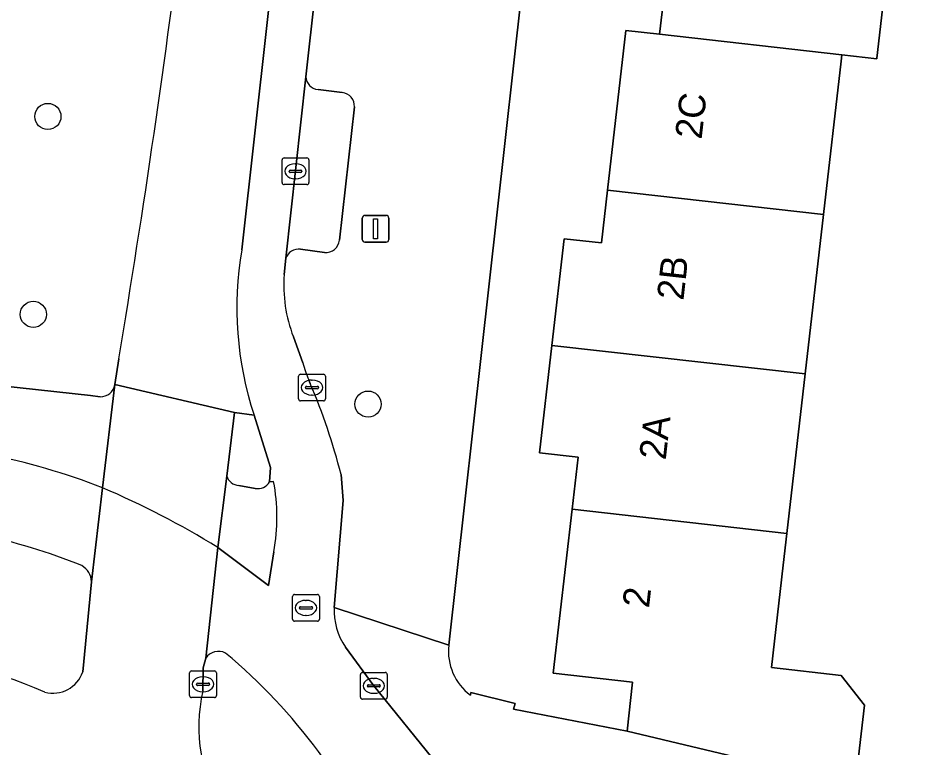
# Model space of a CAD drawing. Extents: x 162026 to 163502, y 387295 to 388169.
# Drawn here: x 162355.04 to 162389.15, y 387412.57 to 387439.84 of the extents above; entities that cross this region are included whole.
import ezdxf

# ---------------------------------------------------------------- set-up
doc = ezdxf.new("R2010")
doc.units = 0
for name, color, linetype in [('IMGEO_Berm_groen', 7, 'Continuous'), ('IMGEO_Boom', 7, 'Continuous'), ('IMGEO_Erf', 7, 'Continuous'), ('IMGEO_Fietspad_gesloten', 7, 'Continuous'), ('IMGEO_Fietspad_open', 7, 'Continuous'), ('IMGEO_Kolk', 7, 'Continuous'), ('IMGEO_Lichtmast', 7, 'Continuous'), ('IMGEO_Pand', 7, 'Continuous'), ('IMGEO_Pand_nummerreeks', 7, 'Continuous'), ('IMGEO_Parkeervlak_open', 7, 'Continuous'), ('IMGEO_Rijbaan_lokaal_gesloten', 7, 'Continuous'), ('IMGEO_Rioolput', 7, 'Continuous'), ('IMGEO_Verkeerseiland_gesloten', 7, 'Continuous'), ('IMGEO_Verkeerseiland_groen', 7, 'Continuous'), ('IMGEO_Voetpad_open', 7, 'Continuous')]:
    doc.layers.add(name, color=color, linetype=linetype)

msp = doc.modelspace()

# ---------------------------------------------------------------- linework, layer by layer
at = {"layer": 'IMGEO_Berm_groen'}
for points in [[(162358.65, 387426.145), (162358.797, 387427.106)], [(162350.307, 387426.551), (162357.748, 387425.733), (162358.101, 387425.69)]]:
    msp.add_lwpolyline(points, dxfattribs=at)
for centre, radius, start, end in [((161972.176, 387492.017), 392.032, 350.46924, 352.96278), ((162358.124, 387426.221), 0.531, 267.5182, 351.7843)]:
    msp.add_arc(centre, radius, start, end, dxfattribs=at)
at = {"layer": 'IMGEO_Boom'}
for centre in [(162356.148, 387436.17), (162355.605, 387428.77), (162368.117, 387425.414)]:
    msp.add_circle(centre, 0.489, dxfattribs=at)
at = {"layer": 'IMGEO_Erf'}
for points in [[(162377.752, 387439.384), (162379.017, 387439.241), (162379.247, 387441.236), (162378.017, 387441.378), (162378.471, 387445.326), (162378.919, 387449.221), (162380.223, 387449.071), (162380.463, 387451.159), (162381.147, 387457.113), (162383.889, 387456.798), (162384.164, 387459.183), (162377.94, 387459.884), (162376.15, 387460.086), (162376.131, 387460.234), (162376.03, 387460.239), (162375.655, 387456.942), (162371.134, 387416.396)], [(162391.38, 387449.925), (162388.505, 387450.25), (162387.82, 387444.289), (162387.137, 387438.348), (162387.134, 387438.321), (162385.833, 387438.468), (162385.806, 387438.236), (162385.147, 387432.501), (162384.462, 387426.543), (162383.777, 387420.583), (162383.641, 387419.398), (162383.201, 387415.569), (162385.799, 387415.271), (162386.677, 387414.163), (162386.331, 387411.152), (162391.662, 387409.78)], [(162371.947, 387414.533), (162371.957, 387414.634), (162373.616, 387414.217), (162373.56, 387414.003), (162377.809, 387413.191), (162377.999, 387415.013), (162375.039, 387415.353), (162375.743, 387421.481), (162375.967, 387423.431), (162374.533, 387423.596), (162374.994, 387427.606), (162375.453, 387431.599), (162376.839, 387431.44), (162377.066, 387433.415), (162377.752, 387439.384)]]:
    msp.add_lwpolyline(points, dxfattribs=at)
msp.add_arc((162373.162, 387416.172), 2.04, 173.6926, 233.4596, dxfattribs=at)
at = {"layer": 'IMGEO_Fietspad_gesloten'}
for points in [[(162367.941, 387456.884), (162367.962, 387457.104), (162368.361, 387460.854), (162368.714, 387463.921), (162373.113, 387503.254), (162371.444, 387503.441), (162363.403, 387431.184)], [(162364.983, 387430.263), (162365.039, 387430.868), (162365.797, 387437.657), (162367.941, 387456.884)], [(162365.683, 387426.954), (162365.325, 387427.933)], [(162365.958, 387426.183), (162365.928, 387426.252), (162365.9, 387426.321)], [(162363.857, 387425.002), (162364.477, 387423.042), (162364.435, 387422.512), (162364.585, 387422.527)], [(162366.853, 387417.815), (162367.19, 387421.816), (162367.108, 387422.786)], [(162364.59, 387419.896), (162364.392, 387418.637), (162362.502, 387420.059), (162362.048, 387415.912)], [(162370.708, 387411.942), (162368.334, 387414.881), (162367.279, 387416.327)]]:
    msp.add_lwpolyline(points, dxfattribs=at)
for centre, radius, start, end in [((162375.99, 387429.001), 12.775, 170.1593, 198.2411), ((162370.276, 387429.85), 5.309, 175.5359, 201.1647), ((162371.018, 387428.429), 5.535, 195.4568, 202.3879), ((162344.425, 387417), 23.409, 14.3094, 23.096), ((162357.756, 387421.199), 6.957, 349.2097, 11.0081), ((162369.256, 387417.698), 2.406, 177.2096, 214.7422), ((162362.526, 387415.6), 0.571, 62.3062, 146.8162), ((162349.148, 387399.739), 21.306, 22.8824, 50.1851)]:
    msp.add_arc(centre, radius, start, end, dxfattribs=at)
at = {"layer": 'IMGEO_Fietspad_open'}
msp.add_lwpolyline([(162357.784, 387418.776), (162358.194, 387422.286)], dxfattribs=at)
for centre, radius, start, end in [((162349.072, 387398.916), 25.087, 68.6787, 89.1056), ((162349.094, 387398.822), 22.176, 67.942, 88.6487), ((162357.023, 387418.725), 0.763, 3.8485, 58.444)]:
    msp.add_arc(centre, radius, start, end, dxfattribs=at)
at = {"layer": 'IMGEO_Kolk'}
for p, q in [((162364.905, 387433.695), (162364.905, 387434.547)), ((162364.98, 387434.621), (162365.832, 387434.621)), ((162365.906, 387434.547), (162365.906, 387433.695)), ((162365.164, 387434.115), (162365.164, 387434.127)), ((162365.207, 387434.164), (162365.605, 387434.164)), ((162365.393, 387434.401), (162365.418, 387434.401)), ((162365.648, 387434.127), (162365.648, 387434.115)), ((162365.602, 387434.078), (162365.204, 387434.078)), ((162365.416, 387433.841), (162365.391, 387433.841)), ((162365.832, 387433.621), (162364.98, 387433.621)), ((162365.521, 387425.608), (162365.521, 387426.46)), ((162365.596, 387426.534), (162366.448, 387426.534)), ((162366.009, 387426.314), (162366.034, 387426.314)), ((162366.522, 387426.46), (162366.522, 387425.608)), ((162365.78, 387426.028), (162365.78, 387426.04)), ((162366.218, 387425.991), (162365.82, 387425.991)), ((162365.823, 387426.077), (162366.221, 387426.077)), ((162366.264, 387426.04), (162366.264, 387426.028)), ((162366.032, 387425.754), (162366.007, 387425.754)), ((162366.448, 387425.534), (162365.596, 387425.534)), ((162361.447, 387414.515), (162361.447, 387415.367)), ((162361.522, 387415.441), (162362.374, 387415.441)), ((162362.448, 387415.367), (162362.448, 387414.515)), ((162367.908, 387415.381), (162368.76, 387415.381)), ((162361.935, 387415.221), (162361.96, 387415.221)), ((162367.833, 387414.455), (162367.833, 387415.307)), ((162368.321, 387415.161), (162368.346, 387415.161)), ((162368.834, 387415.307), (162368.834, 387414.455)), ((162361.706, 387414.935), (162361.706, 387414.947)), ((162362.144, 387414.898), (162361.746, 387414.898)), ((162361.749, 387414.984), (162362.147, 387414.984)), ((162361.958, 387414.661), (162361.933, 387414.661)), ((162362.19, 387414.947), (162362.19, 387414.935)), ((162368.092, 387414.875), (162368.092, 387414.887)), ((162368.53, 387414.838), (162368.132, 387414.838)), ((162368.135, 387414.924), (162368.533, 387414.924)), ((162368.576, 387414.887), (162368.576, 387414.875)), ((162362.374, 387414.441), (162361.522, 387414.441)), ((162368.76, 387414.381), (162367.908, 387414.381)), ((162368.344, 387414.601), (162368.319, 387414.601))]:
    msp.add_line(p, q, dxfattribs=at)
for points in [[(162364.905, 387433.695), (162364.905, 387434.547)], [(162364.98, 387434.621), (162365.832, 387434.621)], [(162365.906, 387434.547), (162365.906, 387433.695)], [(162365.832, 387433.621), (162364.98, 387433.621)], [(162365.521, 387425.608), (162365.521, 387426.46)], [(162365.596, 387426.534), (162366.448, 387426.534)], [(162366.522, 387426.46), (162366.522, 387425.608)], [(162366.448, 387425.534), (162365.596, 387425.534)], [(162361.447, 387414.515), (162361.447, 387415.367)], [(162361.522, 387415.441), (162362.374, 387415.441)], [(162362.448, 387415.367), (162362.448, 387414.515)], [(162367.908, 387415.381), (162368.76, 387415.381)], [(162367.833, 387414.455), (162367.833, 387415.307)], [(162368.834, 387415.307), (162368.834, 387414.455)], [(162362.374, 387414.441), (162361.522, 387414.441)], [(162368.76, 387414.381), (162367.908, 387414.381)]]:
    msp.add_lwpolyline(points, dxfattribs=at)
for centre, radius, start, end in [((162364.982, 387434.545), 0.0765, 91.552, 178.448), ((162364.982, 387434.545), 0.0765, 91.552, 178.448), ((162365.83, 387434.545), 0.0765, 1.552, 88.448), ((162365.83, 387434.545), 0.0765, 1.552, 88.448), ((162365.204, 387434.124), 0.0403, 85.8775, 175.7526), ((162365.201, 387434.114), 0.0366, 178.938, 274.7102), ((162365.605, 387434.121), 0.043, 264.8664, 352.4533), ((162365.609, 387434.126), 0.0386, 1.7309, 96.639), ((162364.982, 387433.697), 0.0765, 181.552, 268.448), ((162364.982, 387433.697), 0.0765, 181.552, 268.448), ((162365.83, 387433.697), 0.0765, 271.552, 358.448), ((162365.83, 387433.697), 0.0765, 271.552, 358.448), ((162365.598, 387426.458), 0.0765, 91.552, 178.448), ((162365.598, 387426.458), 0.0765, 91.552, 178.448), ((162366.446, 387426.458), 0.0765, 1.552, 88.448), ((162366.446, 387426.458), 0.0765, 1.552, 88.448), ((162365.82, 387426.037), 0.0403, 85.8775, 175.7526), ((162365.817, 387426.027), 0.0366, 178.938, 274.7102), ((162366.221, 387426.034), 0.043, 264.8664, 352.4533), ((162366.225, 387426.039), 0.0386, 1.7309, 96.639), ((162365.598, 387425.61), 0.0765, 181.552, 268.448), ((162365.598, 387425.61), 0.0765, 181.552, 268.448), ((162366.446, 387425.61), 0.0765, 271.552, 358.448), ((162366.446, 387425.61), 0.0765, 271.552, 358.448), ((162361.524, 387415.365), 0.0765, 91.552, 178.448), ((162361.524, 387415.365), 0.0765, 91.552, 178.448), ((162362.372, 387415.365), 0.0765, 1.552, 88.448), ((162362.372, 387415.365), 0.0765, 1.552, 88.448), ((162367.91, 387415.305), 0.0765, 91.552, 178.448), ((162367.91, 387415.305), 0.0765, 91.552, 178.448), ((162368.758, 387415.305), 0.0765, 1.552, 88.448), ((162368.758, 387415.305), 0.0765, 1.552, 88.448), ((162361.746, 387414.944), 0.0403, 85.8775, 175.7526), ((162361.743, 387414.934), 0.0366, 178.938, 274.7102), ((162362.147, 387414.941), 0.043, 264.8664, 352.4533), ((162362.151, 387414.946), 0.0386, 1.7309, 96.639), ((162368.132, 387414.884), 0.0403, 85.8775, 175.7526), ((162368.129, 387414.874), 0.0366, 178.938, 274.7102), ((162368.533, 387414.881), 0.043, 264.8664, 352.4533), ((162368.537, 387414.886), 0.0386, 1.7309, 96.639), ((162361.524, 387414.517), 0.0765, 181.552, 268.448), ((162361.524, 387414.517), 0.0765, 181.552, 268.448), ((162362.372, 387414.517), 0.0765, 271.552, 358.448), ((162362.372, 387414.517), 0.0765, 271.552, 358.448), ((162367.91, 387414.457), 0.0765, 181.552, 268.448), ((162367.91, 387414.457), 0.0765, 181.552, 268.448), ((162368.758, 387414.457), 0.0765, 271.552, 358.448), ((162368.758, 387414.457), 0.0765, 271.552, 358.448)]:
    msp.add_arc(centre, radius, start, end, dxfattribs=at)
for centre, major_axis, ratio, start_param, end_param in [((162365.392, 387434.121), (-0.387, 0.002), 0.722429, 4.712389, 7.853982), ((162365.417, 387434.121), (-0.39, 0.002), 0.717154, 1.570796, 4.712389), ((162366.008, 387426.034), (-0.387, 0.002), 0.722429, 4.712389, 7.853982), ((162366.033, 387426.034), (-0.39, 0.002), 0.717154, 1.570796, 4.712389), ((162361.934, 387414.941), (-0.387, 0.002), 0.722429, 4.712389, 7.853982), ((162361.959, 387414.941), (-0.39, 0.002), 0.717154, 1.570796, 4.712389), ((162368.32, 387414.881), (-0.387, 0.002), 0.722429, 4.712389, 7.853982), ((162368.345, 387414.881), (-0.39, 0.002), 0.717154, 1.570796, 4.712389)]:
    msp.add_ellipse(centre, major_axis=major_axis, ratio=ratio, start_param=start_param, end_param=end_param, dxfattribs=at)
at = {"layer": 'IMGEO_Lichtmast'}
for p, q in [((162368.003, 387432.469), (162368.793, 387432.469)), ((162368.793, 387432.469), (162368.003, 387432.469)), ((162367.903, 387431.569), (162367.903, 387432.369)), ((162367.903, 387432.369), (162367.903, 387431.569)), ((162368.893, 387432.369), (162368.893, 387431.569)), ((162368.893, 387431.569), (162368.893, 387432.369)), ((162368.793, 387431.469), (162368.003, 387431.469)), ((162368.003, 387431.469), (162368.793, 387431.469))]:
    msp.add_line(p, q, dxfattribs=at)
msp.add_lwpolyline([(162368.323, 387432.344), (162368.473, 387432.344), (162368.473, 387431.594), (162368.323, 387431.594), (162368.323, 387432.344)], dxfattribs=at)
for centre, start, end in [((162368.003, 387432.369), 90, 180), ((162368.003, 387432.369), 90, 180), ((162368.793, 387432.369), 0, 90), ((162368.793, 387432.369), 360, 90), ((162368.003, 387431.569), 180, 270), ((162368.003, 387431.569), 180, 270), ((162368.793, 387431.569), 270, 0), ((162368.793, 387431.569), 270, 0)]:
    msp.add_arc(centre, 0.1, start, end, dxfattribs=at)
at = {"layer": 'IMGEO_Pand'}
for points in [[(162387.82, 387444.289), (162378.471, 387445.326), (162378.017, 387441.378), (162379.247, 387441.236), (162379.017, 387439.241), (162385.833, 387438.468), (162387.134, 387438.321), (162387.137, 387438.348)], [(162385.806, 387438.236), (162385.833, 387438.468), (162379.017, 387439.241), (162377.752, 387439.384), (162377.066, 387433.415), (162385.147, 387432.501)], [(162384.462, 387426.543), (162385.147, 387432.501), (162377.066, 387433.415), (162376.839, 387431.44), (162375.453, 387431.599), (162374.994, 387427.606)], [(162374.994, 387427.606), (162374.533, 387423.596), (162375.967, 387423.431), (162375.743, 387421.481), (162383.777, 387420.583), (162384.462, 387426.543)], [(162386.331, 387411.152), (162386.677, 387414.163), (162385.799, 387415.271), (162383.201, 387415.569), (162383.641, 387419.398), (162383.777, 387420.583), (162375.743, 387421.481), (162375.039, 387415.353), (162377.999, 387415.013), (162377.809, 387413.191)]]:
    msp.add_lwpolyline(points, close=True, dxfattribs=at)
at = {"layer": 'IMGEO_Parkeervlak_open'}
for points in [[(162365.797, 387437.657), (162365.039, 387430.868)], [(162367.15, 387437.065), (162366.247, 387437.181)], [(162367.044, 387431.55), (162367.605, 387436.524)], [(162365.588, 387431.204), (162366.491, 387431.081)]]:
    msp.add_lwpolyline(points, dxfattribs=at)
for centre, radius, start, end in [((162366.278, 387437.661), 0.481, 180.5235, 266.2599), ((162367.106, 387436.566), 0.501, 355.1616, 84.9684), ((162366.538, 387431.587), 0.508, 264.7368, 355.8658), ((162365.529, 387430.684), 0.523, 83.4861, 159.449)]:
    msp.add_arc(centre, radius, start, end, dxfattribs=at)
at = {"layer": 'IMGEO_Rijbaan_lokaal_gesloten'}
for points in [[(162363.403, 387431.184), (162371.444, 387503.441)], [(162358.797, 387427.106), (162358.65, 387426.145), (162363.12, 387425.103), (162363.857, 387425.002)], [(162363.12, 387425.103), (162358.65, 387426.145), (162358.194, 387422.286)], [(162362.502, 387420.059), (162362.838, 387422.726), (162363.12, 387425.103)], [(162358.194, 387422.286), (162357.784, 387418.776), (162357.454, 387415.406)], [(162361.944, 387414.691), (162361.957, 387415.56), (162362.048, 387415.912), (162362.502, 387420.059)]]:
    msp.add_lwpolyline(points, dxfattribs=at)
for centre, radius, start, end in [((161972.176, 387492.017), 392.032, 350.46924, 352.96278), ((162375.99, 387429.001), 12.775, 170.1593, 198.2411), ((162345.125, 387391.724), 33.239, 58.4801, 66.8469), ((162345.125, 387391.724), 33.239, 58.4801, 66.8469), ((162349.016, 387398.466), 17.639, 66.5666, 87.9058), ((162356.344, 387415.778), 1.17, 254.4829, 341.478), ((162367.693, 387413.342), 5.905, 166.7956, 258.967)]:
    msp.add_arc(centre, radius, start, end, dxfattribs=at)
at = {"layer": 'IMGEO_Rioolput'}
for p, q in [((162365.296, 387417.371), (162365.296, 387418.223)), ((162365.371, 387418.297), (162366.223, 387418.297)), ((162365.784, 387418.077), (162365.809, 387418.077)), ((162366.297, 387418.223), (162366.297, 387417.371)), ((162365.555, 387417.791), (162365.555, 387417.803)), ((162365.993, 387417.754), (162365.595, 387417.754)), ((162365.598, 387417.84), (162365.996, 387417.84)), ((162366.039, 387417.803), (162366.039, 387417.791)), ((162365.807, 387417.517), (162365.782, 387417.517)), ((162366.223, 387417.297), (162365.371, 387417.297))]:
    msp.add_line(p, q, dxfattribs=at)
for points in [[(162365.296, 387417.371), (162365.296, 387418.223)], [(162365.371, 387418.297), (162366.223, 387418.297)], [(162366.297, 387418.223), (162366.297, 387417.371)], [(162366.223, 387417.297), (162365.371, 387417.297)]]:
    msp.add_lwpolyline(points, dxfattribs=at)
for centre, radius, start, end in [((162365.373, 387418.221), 0.0765, 91.552, 178.448), ((162365.373, 387418.221), 0.0765, 91.552, 178.448), ((162366.221, 387418.221), 0.0765, 1.552, 88.448), ((162366.221, 387418.221), 0.0765, 1.552, 88.448), ((162365.595, 387417.8), 0.0403, 85.8775, 175.7526), ((162365.592, 387417.79), 0.0366, 178.938, 274.7102), ((162365.996, 387417.797), 0.043, 264.8664, 352.4533), ((162366, 387417.802), 0.0386, 1.7309, 96.639), ((162365.373, 387417.373), 0.0765, 181.552, 268.448), ((162365.373, 387417.373), 0.0765, 181.552, 268.448), ((162366.221, 387417.373), 0.0765, 271.552, 358.448), ((162366.221, 387417.373), 0.0765, 271.552, 358.448)]:
    msp.add_arc(centre, radius, start, end, dxfattribs=at)
for centre, major_axis, ratio, start_param, end_param in [((162365.783, 387417.797), (-0.387, 0.002), 0.722429, 4.712389, 7.853982), ((162365.808, 387417.797), (-0.39, 0.002), 0.717154, 1.570796, 4.712389)]:
    msp.add_ellipse(centre, major_axis=major_axis, ratio=ratio, start_param=start_param, end_param=end_param, dxfattribs=at)
at = {"layer": 'IMGEO_Verkeerseiland_gesloten'}
for points in [[(162363.857, 387425.002), (162363.12, 387425.103), (162362.838, 387422.726)], [(162364.435, 387422.512), (162364.477, 387423.042), (162363.857, 387425.002)], [(162363.283, 387422.376), (162363.899, 387422.264)]]:
    msp.add_lwpolyline(points, dxfattribs=at)
for centre, radius, start, end in [((162363.31, 387422.868), 0.493, 196.7854, 266.8433), ((162363.994, 387422.762), 0.507, 259.2161, 330.4426)]:
    msp.add_arc(centre, radius, start, end, dxfattribs=at)
at = {"layer": 'IMGEO_Verkeerseiland_groen'}
for points in [[(162357.454, 387415.406), (162357.784, 387418.776)], [(162362.048, 387415.912), (162361.957, 387415.56), (162361.944, 387414.691)]]:
    msp.add_lwpolyline(points, dxfattribs=at)
for centre, radius, start, end in [((162349.094, 387398.822), 22.176, 67.942, 88.6487), ((162357.023, 387418.725), 0.763, 3.8485, 58.444), ((162349.016, 387398.466), 17.639, 66.5666, 87.9058), ((162362.526, 387415.6), 0.571, 62.3062, 146.8162), ((162349.148, 387399.739), 21.306, 22.8824, 50.1851), ((162356.344, 387415.778), 1.17, 254.4829, 341.478), ((162367.693, 387413.342), 5.905, 166.7956, 258.967)]:
    msp.add_arc(centre, radius, start, end, dxfattribs=at)
at = {"layer": 'IMGEO_Voetpad_open'}
for points in [[(162368.714, 387463.921), (162368.361, 387460.854), (162367.962, 387457.104), (162367.941, 387456.884), (162365.797, 387437.657)], [(162367.108, 387422.786), (162367.19, 387421.816), (162366.853, 387417.815), (162371.134, 387416.396), (162375.655, 387456.942), (162376.03, 387460.239), (162376.131, 387460.234), (162376.477, 387463.277)], [(162366.247, 387437.181), (162367.15, 387437.065)], [(162367.605, 387436.524), (162367.044, 387431.55)], [(162366.491, 387431.081), (162365.588, 387431.204)], [(162365.039, 387430.868), (162364.983, 387430.263)], [(162365.325, 387427.933), (162365.683, 387426.954)], [(162358.101, 387425.69), (162357.748, 387425.733), (162350.307, 387426.551)], [(162365.9, 387426.321), (162365.928, 387426.252), (162365.958, 387426.183)], [(162358.194, 387422.286), (162358.65, 387426.145)], [(162362.838, 387422.726), (162362.502, 387420.059), (162364.392, 387418.637), (162364.59, 387419.896)], [(162364.585, 387422.527), (162364.435, 387422.512)], [(162363.899, 387422.264), (162363.283, 387422.376)], [(162371.134, 387416.396), (162366.853, 387417.815)], [(162367.279, 387416.327), (162368.334, 387414.881), (162370.708, 387411.942)], [(162452.941, 387395.422), (162447.498, 387396.697), (162442.45, 387397.88), (162424.994, 387401.97), (162404.454, 387406.677), (162397.856, 387408.293), (162396.253, 387408.686), (162394.477, 387409.121), (162391.662, 387409.78), (162386.331, 387411.152), (162377.809, 387413.191), (162373.56, 387414.003), (162373.616, 387414.217), (162371.957, 387414.634), (162371.947, 387414.533)]]:
    msp.add_lwpolyline(points, dxfattribs=at)
for centre, radius, start, end in [((162366.278, 387437.661), 0.481, 180.5235, 266.2599), ((162367.106, 387436.566), 0.501, 355.1616, 84.9684), ((162366.538, 387431.587), 0.508, 264.7368, 355.8658), ((162365.529, 387430.684), 0.523, 83.4861, 159.449), ((162370.276, 387429.85), 5.309, 175.5359, 201.1647), ((162371.018, 387428.429), 5.535, 195.4568, 202.3879), ((162358.124, 387426.221), 0.531, 267.5182, 351.7843), ((162344.425, 387417), 23.409, 14.3094, 23.096), ((162349.072, 387398.916), 25.087, 68.6787, 89.1056), ((162363.31, 387422.868), 0.493, 196.7854, 266.8433), ((162363.994, 387422.762), 0.507, 259.2161, 330.4426), ((162357.756, 387421.199), 6.957, 349.2097, 11.0081), ((162369.256, 387417.698), 2.406, 177.2096, 214.7422), ((162373.162, 387416.172), 2.04, 173.6926, 233.4596)]:
    msp.add_arc(centre, radius, start, end, dxfattribs=at)

# ---------------------------------------------------------------- texts
at = {"layer": 'IMGEO_Pand_nummerreeks'}
for s, rotation, p in [('2C', 83.4456, (162380.584, 387435.294)), ('2B', 83.6731, (162379.906, 387429.271)), ('2A', 83.6659, (162379.244, 387423.303)), ('2', 83.4557, (162378.618, 387417.767))]:
    msp.add_text(s, height=1, rotation=rotation, dxfattribs=at).set_placement(p)

doc.saveas('drawing.dxf')
